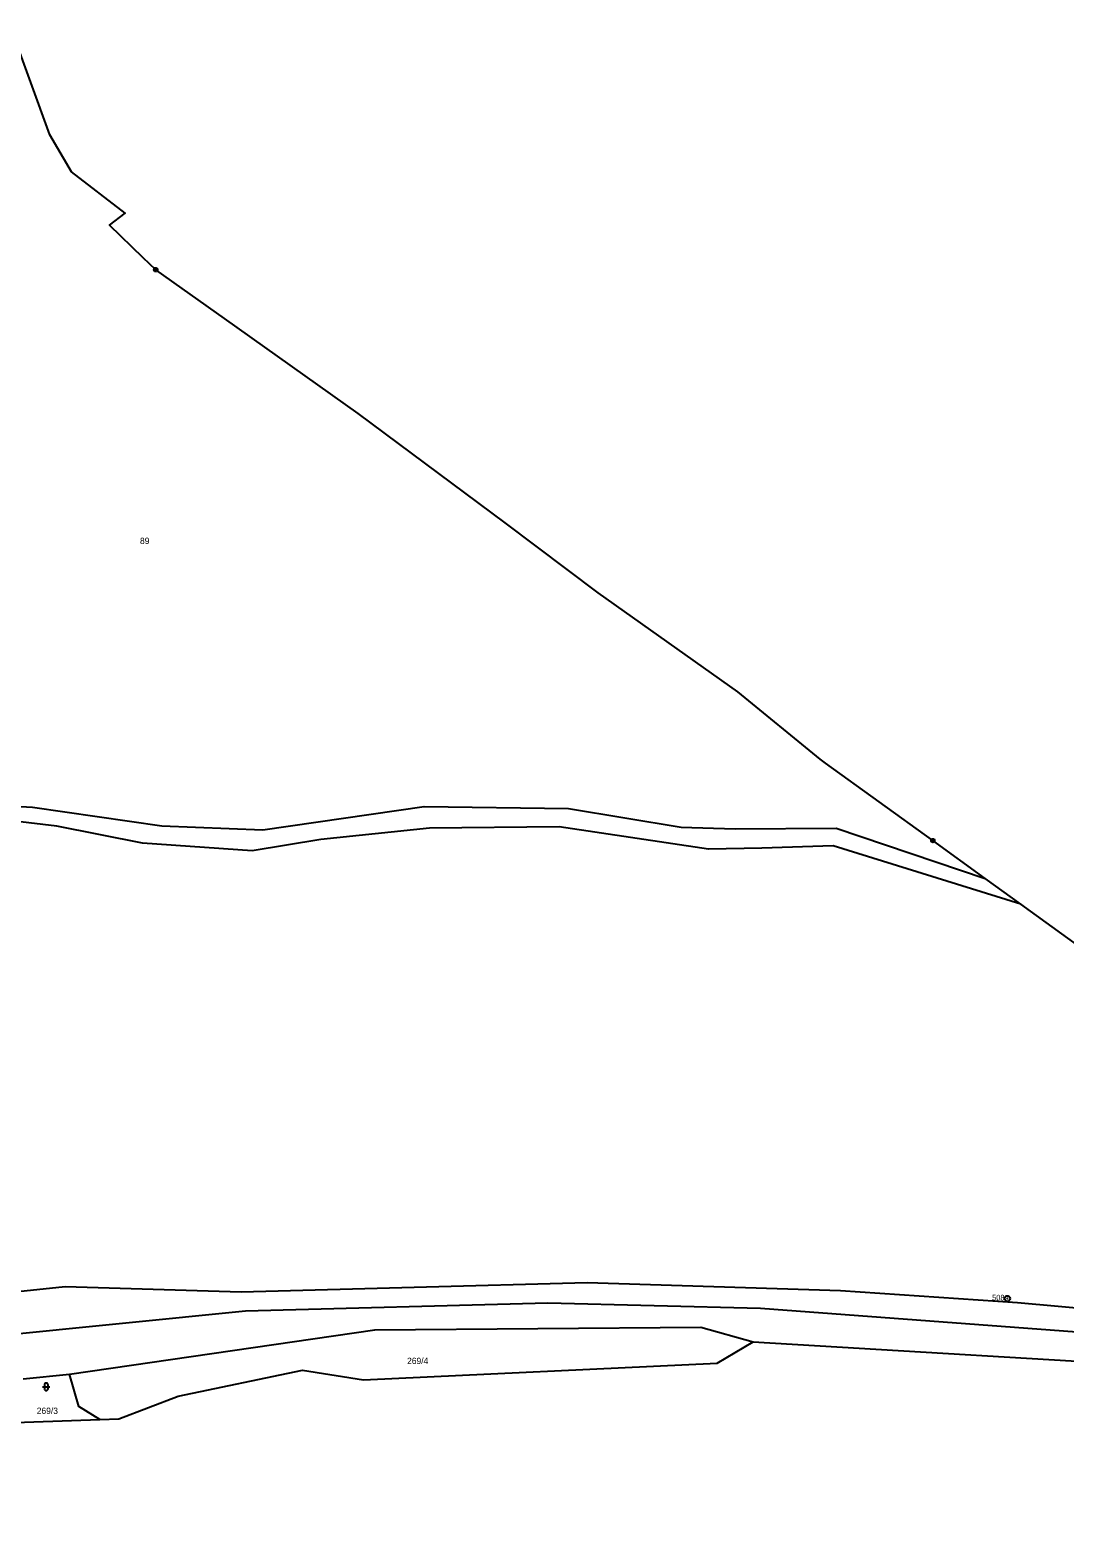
# Model space of a CAD drawing. Extents: x -779723 to -777378, y -1011169 to -1009297.
# Drawn here: x -778181.3 to -777903.5, y -1010301 to -1009896 of the extents above; entities that cross this region are included whole.
import ezdxf

# ---------------------------------------------------------------- set-up
doc = ezdxf.new("R2010")
doc.units = 0
for name, color, linetype in [('Hranice parcel', 7, 'Continuous'), ('Parcelní čísla', 7, 'Continuous'), ('Poz předměty', 7, 'Continuous'), ('Značky bodu BP', 7, 'Continuous'), ('Značky kultur', 7, 'Continuous')]:
    doc.layers.add(name, color=color, linetype=linetype)

msp = doc.modelspace()

# ---------------------------------------------------------------- linework, layer by layer
at = {"layer": 'Hranice parcel'}
for p, q in [((-778176.01, -1009924.09), (-778186.19, -1009895.98)), ((-777924.86, -1010123.86), (-777938.89, -1010113.7)), ((-777915.32, -1010130.76), (-777924.86, -1010123.86)), ((-778183.15, -1010258.35), (-778170.74, -1010257.06)), ((-778193.74, -1010270.34), (-778162.58, -1010269.25))]:
    msp.add_line(p, q, dxfattribs=at)
for points in [[(-778147.56, -1009960.33), (-778150.97, -1009957.16), (-778159.95, -1009948.33), (-778155.75, -1009945.17), (-778170.19, -1009934.08), (-778176.01, -1009924.09)], [(-778093.24, -1009998.98), (-778129.11, -1009973.45), (-778147.56, -1009960.33)], [(-777938.89, -1010113.7), (-777967.71, -1010092.87), (-777969.15, -1010091.83), (-777991.28, -1010073.76), (-778028.76, -1010047.15), (-778053.72, -1010028.31), (-778093.24, -1009998.98)], [(-777915.32, -1010130.76), (-777965.67, -1010115.09), (-777984.81, -1010115.73), (-777999.17, -1010116.04), (-778039.22, -1010109.98), (-778074.01, -1010110.38), (-778103.23, -1010113.41), (-778121.64, -1010116.47), (-778151.12, -1010114.44), (-778174.14, -1010109.8), (-778185.39, -1010108.53), (-778237.09, -1010105.96), (-778294.76, -1010098.57), (-778302.43, -1010096.77), (-778365.7, -1010080.27), (-778423.7, -1010062.57), (-778466.13, -1010049.97), (-778520.34, -1010042.8)], [(-778507.76, -1010041.04), (-778463.16, -1010047.36), (-778448.54, -1010051.05), (-778413.41, -1010061.34), (-778360.73, -1010076.84), (-778296.58, -1010094.47), (-778291.4, -1010095.84), (-778239.95, -1010101.4), (-778180.65, -1010104.69), (-778145.9, -1010109.73), (-778118.76, -1010110.86), (-778075.46, -1010104.51), (-778036.74, -1010105.05), (-778006.46, -1010110.09), (-777991.99, -1010110.55), (-777964.85, -1010110.4), (-777924.86, -1010123.86)], [(-777760.11, -1010255.16), (-777806.93, -1010215.01), (-777861.25, -1010169.9), (-777915.32, -1010130.76)], [(-778491.82, -1010293.76), (-778486.94, -1010292.24), (-778480.1, -1010293.71), (-778465.61, -1010291.22), (-778453.63, -1010290.98), (-778416.45, -1010285.13), (-778355.22, -1010269.42), (-778205.12, -1010236.96), (-778171.83, -1010233.51), (-778124.65, -1010234.94), (-778031.73, -1010232.44), (-777963.69, -1010234.58), (-777916.19, -1010237.79), (-777862.6, -1010242.68), (-777843.18, -1010245), (-777757.95, -1010256.86)], [(-778170.74, -1010257.06), (-778088.74, -1010245.14), (-778001.23, -1010244.44), (-777987.12, -1010248.38)], [(-778162.58, -1010269.25), (-778157.45, -1010269.07), (-778141.57, -1010263.01), (-778108.14, -1010255.99), (-778091.73, -1010258.61), (-777996.83, -1010254.14), (-777987.12, -1010248.38)], [(-777987.12, -1010248.38), (-777867.3, -1010255.54), (-777840.84, -1010256.64), (-777764.7, -1010269.46), (-777752.89, -1010289.37), (-777741.89, -1010301.03), (-777729.99, -1010278.87)], [(-778162.58, -1010269.25), (-778168.18, -1010265.77), (-778170.74, -1010257.06)]]:
    msp.add_lwpolyline(points, dxfattribs=at)
at = {"layer": 'Poz předměty'}
for p, q in [((-778123.44, -1010240), (-778042.28, -1010237.85)), ((-778042.28, -1010237.85), (-777985.16, -1010239.29)), ((-778203.65, -1010248.13), (-778123.44, -1010240)), ((-777985.16, -1010239.29), (-777867.19, -1010248.13))]:
    msp.add_line(p, q, dxfattribs=at)
at = {"layer": 'Značky bodu BP'}
for centre, radius in [((-778147.56, -1009960.33), 0.5), ((-778147.56, -1009960.33), 0.5), ((-778147.56, -1009960.33), 0.5), ((-778147.56, -1009960.33), 0.0303), ((-778147.56, -1009960.33), 0.0303), ((-778147.56, -1009960.33), 0.0303), ((-777938.89, -1010113.7), 0.5), ((-777938.89, -1010113.7), 0.0303), ((-777918.91, -1010236.74), 0.75), ((-777918.91, -1010236.74), 0.03)]:
    msp.add_circle(centre, radius, dxfattribs=at)
at = {"layer": 'Značky kultur'}
for p, q in [((-778177.96, -1010260.44), (-778175.96, -1010260.44)), ((-778177.46, -1010259.94), (-778177.46, -1010260.94)), ((-778176.46, -1010260.94), (-778176.46, -1010259.94))]:
    msp.add_line(p, q, dxfattribs=at)
for centre, start, end in [((-778176.96, -1010259.94), 0, 180), ((-778176.96, -1010260.94), 180, 359.9879)]:
    msp.add_arc(centre, 0.5, start, end, dxfattribs=at)

# ---------------------------------------------------------------- texts
at = {"layer": 'Parcelní čísla'}
for s, p in [('89', (-778151.78, -1010034.04)), ('269/4', (-778080.07, -1010254.34)), ('269/3', (-778179.5, -1010267.74))]:
    msp.add_text(s, height=1.7, dxfattribs=at).set_placement(p)
at = {"layer": 'Značky bodu BP'}
msp.add_text('508', height=1.5, dxfattribs=at).set_placement((-777923.01, -1010237.24))

doc.saveas('drawing.dxf')
